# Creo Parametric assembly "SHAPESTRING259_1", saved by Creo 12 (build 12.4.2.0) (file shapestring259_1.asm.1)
Units: Custom; MM, KILOGRAM, SECS

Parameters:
  PTC_WM_ITERATION = "0"
  PTC_WM_VERSION = "-.0"
  PTC_WM_LIFECYCLE_STATE = "In Work"
  PTC_WM_LIFECYCLE = "MO_CADDocument"
  PTC_WM_CREATED_BY = "Maximilian Roepper (Z0017RMS: MO)"
  PTC_WM_CREATED_ON = "18-Sep-26 11:36:42 AM"
  PTC_WM_MODIFIED_BY = "Maximilian Roepper (Z0017RMS: MO)"
  PTC_WM_MODIFIED_ON = "18-Sep-26 11:36:46 AM"
  PDMLINKNUMBER = "PDM000071455349"
  PTC_WM_NUMBER = "PDM000071455349"

Other parameters: WEIGHT, WEIGHT_FACTOR, WEIGHT_ADD, MC_ERRORS, SUPPLIER

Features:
  1. coordinate system
  2. imported feature
  3. component "SHAPESTRING002_1"
  4. component "SHAPESTRING257_1"
  5. component "SHAPESTRING258_1"

Other named items: DRW_VIEW_ORG, ROUGH-GROB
